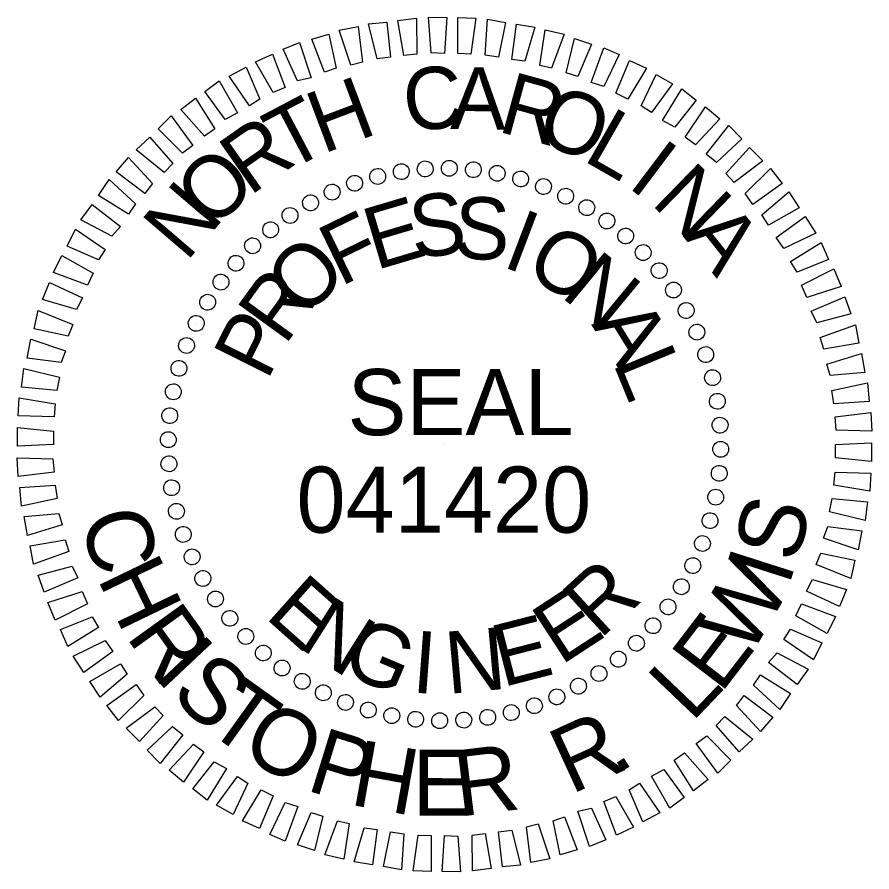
# Model space of a CAD drawing. Extents: x 573468 to 580768, y -57414 to -51768.
# Drawn here: x 580690.5 to 580768.1, y -52057.1 to -51979.5 of the extents above; entities that cross this region are included whole.
import ezdxf

# ---------------------------------------------------------------- set-up
doc = ezdxf.new("R2010")
doc.units = 0
doc.layers.add('Sheet PE Seal Cell', color=7, linetype='Continuous')

msp = doc.modelspace()

# ---------------------------------------------------------------- linework, layer by layer
at = {"layer": 'Sheet PE Seal Cell'}
for p, q in [((580725.379, -51993.539), (580725.379, -51993.539)), ((580727.529, -51993.239), (580727.529, -51993.239)), ((580729.729, -51993.189), (580729.729, -51993.189)), ((580731.929, -51993.339), (580731.929, -51993.339)), ((580723.179, -51993.939), (580723.179, -51993.939)), ((580734.079, -51993.689), (580734.079, -51993.689)), ((580736.179, -51994.139), (580736.179, -51994.139)), ((580721.079, -51994.539), (580721.079, -51994.539)), ((580738.279, -51994.839), (580738.279, -51994.839)), ((580719.079, -51995.339), (580719.079, -51995.339)), ((580740.279, -51995.739), (580740.279, -51995.739)), ((580717.129, -51996.339), (580717.129, -51996.339)), ((580742.229, -51996.739), (580742.229, -51996.739)), ((580715.229, -51997.489), (580715.229, -51997.489)), ((580744.029, -51997.989), (580744.029, -51997.989)), ((580713.479, -51998.739), (580713.479, -51998.739)), ((580745.779, -51999.339), (580745.779, -51999.339)), ((580711.829, -52000.239), (580711.829, -52000.239)), ((580747.329, -52000.839), (580747.329, -52000.839)), ((580710.329, -52001.789), (580710.329, -52001.789)), ((580748.829, -52002.489), (580748.829, -52002.489)), ((580708.979, -52003.539), (580708.979, -52003.539)), ((580750.079, -52004.239), (580750.079, -52004.239)), ((580707.729, -52005.339), (580707.729, -52005.339)), ((580751.229, -52006.139), (580751.229, -52006.139)), ((580706.729, -52007.289), (580706.729, -52007.289)), ((580752.229, -52008.089), (580752.229, -52008.089)), ((580705.829, -52009.289), (580705.829, -52009.289)), ((580753.029, -52010.089), (580753.029, -52010.089)), ((580705.129, -52011.389), (580705.129, -52011.389)), ((580753.629, -52012.189), (580753.629, -52012.189)), ((580704.679, -52013.489), (580704.679, -52013.489)), ((580754.029, -52014.389), (580754.029, -52014.389)), ((580704.329, -52015.639), (580704.329, -52015.639)), ((580754.329, -52016.539), (580754.329, -52016.539)), ((580704.179, -52017.839), (580704.179, -52017.839)), ((580729.279, -52018.289), (580729.279, -52018.289)), ((580754.379, -52018.739), (580754.379, -52018.739)), ((580704.229, -52020.039), (580704.229, -52020.039)), ((580754.229, -52020.939), (580754.229, -52020.939)), ((580704.529, -52022.189), (580704.529, -52022.189)), ((580753.879, -52023.089), (580753.879, -52023.089)), ((580704.929, -52024.389), (580704.929, -52024.389)), ((580753.429, -52025.189), (580753.429, -52025.189)), ((580705.529, -52026.489), (580705.529, -52026.489)), ((580752.729, -52027.289), (580752.729, -52027.289)), ((580706.329, -52028.489), (580706.329, -52028.489)), ((580751.829, -52029.289), (580751.829, -52029.289)), ((580707.329, -52030.439), (580707.329, -52030.439)), ((580750.829, -52031.239), (580750.829, -52031.239)), ((580708.479, -52032.339), (580708.479, -52032.339)), ((580749.579, -52033.039), (580749.579, -52033.039)), ((580709.729, -52034.089), (580709.729, -52034.089)), ((580748.229, -52034.789), (580748.229, -52034.789)), ((580711.229, -52035.739), (580711.229, -52035.739)), ((580746.729, -52036.339), (580746.729, -52036.339)), ((580712.779, -52037.239), (580712.779, -52037.239)), ((580745.079, -52037.839), (580745.079, -52037.839)), ((580714.529, -52038.589), (580714.529, -52038.589)), ((580743.329, -52039.089), (580743.329, -52039.089)), ((580716.329, -52039.839), (580716.329, -52039.839)), ((580718.279, -52040.839), (580718.279, -52040.839)), ((580741.429, -52040.239), (580741.429, -52040.239)), ((580739.479, -52041.239), (580739.479, -52041.239)), ((580720.279, -52041.739), (580720.279, -52041.739)), ((580722.379, -52042.439), (580722.379, -52042.439)), ((580737.479, -52042.039), (580737.479, -52042.039)), ((580724.479, -52042.889), (580724.479, -52042.889)), ((580733.179, -52043.039), (580733.179, -52043.039)), ((580735.379, -52042.639), (580735.379, -52042.639)), ((580726.629, -52043.239), (580726.629, -52043.239)), ((580728.829, -52043.389), (580728.829, -52043.389)), ((580731.029, -52043.339), (580731.029, -52043.339))]:
    msp.add_line(p, q, dxfattribs=at)
for points in [[(580728.079, -51982.739), (580727.829, -51979.489), (580729.479, -51979.539), (580729.279, -51982.789)], [(580730.479, -51982.789), (580730.479, -51979.539), (580732.129, -51979.589), (580731.679, -51982.839)], [(580720.779, -51983.839), (580719.729, -51980.689), (580721.429, -51980.339), (580721.829, -51983.589)], [(580723.179, -51983.289), (580722.379, -51980.089), (580724.029, -51979.939), (580724.379, -51983.139)], [(580725.579, -51982.989), (580725.029, -51979.789), (580726.729, -51979.589), (580726.779, -51982.839)], [(580732.979, -51982.939), (580733.179, -51979.689), (580734.829, -51979.989), (580734.179, -51983.139)], [(580735.379, -51983.339), (580735.829, -51980.139), (580737.479, -51980.389), (580736.579, -51983.489)], [(580718.379, -51984.489), (580717.229, -51981.489), (580718.779, -51981.039), (580719.429, -51984.139)], [(580737.929, -51983.889), (580738.429, -51980.639), (580740.129, -51981.039), (580738.979, -51984.139)], [(580715.929, -51985.289), (580714.629, -51982.389), (580716.129, -51981.789), (580717.179, -51984.989)], [(580740.329, -51984.539), (580741.079, -51981.439), (580742.629, -51981.939), (580741.379, -51984.889)], [(580742.579, -51985.439), (580743.729, -51982.289), (580745.129, -51982.889), (580743.729, -51985.789)], [(580713.729, -51986.339), (580712.129, -51983.539), (580713.679, -51982.839), (580714.829, -51985.889)], [(580744.829, -51986.389), (580746.079, -51983.439), (580747.629, -51984.139), (580745.929, -51986.939)], [(580711.579, -51987.539), (580709.729, -51984.839), (580711.279, -51984.039), (580712.529, -51986.939)], [(580747.129, -51987.539), (580748.479, -51984.689), (580749.979, -51985.539), (580748.079, -51988.139)], [(580709.379, -51988.789), (580707.529, -51986.239), (580708.829, -51985.289), (580710.479, -51988.189)], [(580749.079, -51988.889), (580750.829, -51985.989), (580752.129, -51987.039), (580750.179, -51989.489)], [(580707.479, -51990.289), (580705.329, -51987.889), (580706.679, -51986.839), (580708.429, -51989.639)], [(580751.129, -51990.389), (580752.979, -51987.639), (580754.279, -51988.739), (580752.079, -51991.089)], [(580705.479, -51991.839), (580703.279, -51989.639), (580704.479, -51988.439), (580706.429, -51991.139)], [(580753.029, -51991.939), (580755.079, -51989.339), (580756.279, -51990.539), (580753.979, -51992.689)], [(580703.829, -51993.589), (580701.279, -51991.539), (580702.529, -51990.389), (580704.629, -51992.789)], [(580754.829, -51993.689), (580756.979, -51991.339), (580758.179, -51992.539), (580755.579, -51994.489)], [(580702.079, -51995.489), (580699.479, -51993.539), (580700.579, -51992.239), (580702.779, -51994.589)], [(580756.579, -51995.489), (580758.879, -51993.239), (580759.929, -51994.589), (580757.279, -51996.489)], [(580700.579, -51997.389), (580697.879, -51995.689), (580698.829, -51994.239), (580701.229, -51996.439)], [(580758.079, -51997.439), (580760.529, -51995.339), (580761.479, -51996.789), (580758.679, -51998.389)], [(580699.079, -51999.389), (580696.279, -51997.889), (580697.279, -51996.489), (580699.879, -51998.489)], [(580759.379, -51999.489), (580762.029, -51997.589), (580762.979, -51999.089), (580760.079, -52000.489)], [(580697.879, -52001.539), (580695.029, -52000.289), (580695.779, -51998.739), (580698.479, -52000.589)], [(580760.679, -52001.689), (580763.479, -51999.939), (580764.129, -52001.489), (580761.279, -52002.639)], [(580696.879, -52003.839), (580693.779, -52002.689), (580694.529, -52001.139), (580697.379, -52002.739)], [(580761.679, -52003.839), (580764.629, -52002.339), (580765.279, -52003.939), (580762.179, -52004.939)], [(580695.879, -52006.039), (580692.779, -52005.139), (580693.429, -52003.589), (580696.429, -52004.989)], [(580762.579, -52006.189), (580765.629, -52004.889), (580766.179, -52006.439), (580763.079, -52007.239)], [(580695.129, -52008.439), (580692.029, -52007.789), (580692.379, -52006.139), (580695.529, -52007.389)], [(580763.379, -52008.589), (580766.579, -52007.439), (580766.879, -52009.089), (580763.729, -52009.639)], [(580694.479, -52010.839), (580691.379, -52010.439), (580691.729, -52008.739), (580694.879, -52009.789)], [(580763.979, -52010.989), (580767.129, -52010.039), (580767.429, -52011.739), (580764.279, -52012.039)], [(580694.079, -52013.389), (580690.879, -52013.089), (580691.079, -52011.389), (580694.329, -52012.189)], [(580764.429, -52013.389), (580767.679, -52012.689), (580767.829, -52014.389), (580764.629, -52014.589)], [(580693.829, -52015.789), (580690.579, -52015.689), (580690.679, -52014.039), (580693.929, -52014.589)], [(580764.729, -52015.789), (580767.979, -52015.389), (580768.079, -52017.089), (580764.829, -52016.989)], [(580693.779, -52018.289), (580690.529, -52018.439), (580690.529, -52016.739), (580693.779, -52017.089)], [(580764.779, -52018.289), (580768.029, -52018.139), (580768.029, -52019.839), (580764.779, -52019.489)], [(580693.829, -52020.789), (580690.579, -52021.189), (580690.479, -52019.489), (580693.729, -52019.589)], [(580764.729, -52020.789), (580767.979, -52020.889), (580767.879, -52022.539), (580764.629, -52021.989)], [(580694.129, -52023.189), (580690.879, -52023.889), (580690.729, -52022.189), (580693.929, -52021.989)], [(580764.479, -52023.189), (580767.679, -52023.489), (580767.479, -52025.189), (580764.229, -52024.389)], [(580694.579, -52025.589), (580691.429, -52026.539), (580691.129, -52024.839), (580694.279, -52024.539)], [(580764.079, -52025.739), (580767.179, -52026.139), (580766.829, -52027.839), (580763.679, -52026.789)], [(580695.179, -52027.989), (580691.979, -52029.139), (580691.679, -52027.489), (580694.829, -52026.939)], [(580763.429, -52028.139), (580766.529, -52028.789), (580766.179, -52030.439), (580763.029, -52029.189)], [(580695.979, -52030.389), (580692.929, -52031.689), (580692.379, -52030.139), (580695.479, -52029.339)], [(580762.679, -52030.539), (580765.779, -52031.439), (580765.129, -52032.989), (580762.129, -52031.589)], [(580696.879, -52032.739), (580693.929, -52034.239), (580693.279, -52032.639), (580696.379, -52031.639)], [(580761.679, -52032.739), (580764.779, -52033.889), (580764.029, -52035.439), (580761.179, -52033.839)], [(580697.879, -52034.889), (580695.079, -52036.639), (580694.429, -52035.089), (580697.279, -52033.939)], [(580760.679, -52035.039), (580763.529, -52036.289), (580762.779, -52037.839), (580760.079, -52035.989)], [(580699.179, -52037.089), (580696.529, -52038.989), (580695.579, -52037.489), (580698.479, -52036.089)], [(580759.479, -52037.189), (580762.279, -52038.689), (580761.279, -52040.089), (580758.679, -52038.089)], [(580700.479, -52039.139), (580698.029, -52041.239), (580697.079, -52039.789), (580699.879, -52038.189)], [(580757.979, -52039.189), (580760.679, -52040.889), (580759.729, -52042.339), (580757.329, -52040.139)], [(580701.979, -52041.089), (580699.679, -52043.339), (580698.629, -52041.989), (580701.279, -52040.089)], [(580756.479, -52041.089), (580759.079, -52043.039), (580757.979, -52044.339), (580755.779, -52041.989)], [(580703.729, -52042.889), (580701.579, -52045.239), (580700.379, -52044.039), (580702.979, -52042.089)], [(580754.729, -52042.989), (580757.279, -52045.039), (580756.029, -52046.189), (580753.929, -52043.789)], [(580705.529, -52044.639), (580703.479, -52047.239), (580702.279, -52046.039), (580704.579, -52043.889)], [(580753.079, -52044.739), (580755.279, -52046.939), (580754.079, -52048.139), (580752.129, -52045.439)], [(580707.429, -52046.189), (580705.579, -52048.939), (580704.279, -52047.839), (580706.479, -52045.489)], [(580751.079, -52046.289), (580753.229, -52048.689), (580751.879, -52049.739), (580750.129, -52046.939)], [(580709.479, -52047.689), (580707.729, -52050.589), (580706.429, -52049.539), (580708.379, -52047.089)], [(580749.179, -52047.789), (580751.029, -52050.339), (580749.729, -52051.289), (580748.079, -52048.389)], [(580711.429, -52049.039), (580710.079, -52051.889), (580708.579, -52051.039), (580710.479, -52048.439)], [(580746.979, -52049.039), (580748.829, -52051.739), (580747.279, -52052.539), (580746.029, -52049.639)], [(580713.729, -52050.189), (580712.479, -52053.139), (580710.929, -52052.439), (580712.629, -52049.639)], [(580715.979, -52051.139), (580714.829, -52054.289), (580713.429, -52053.689), (580714.829, -52050.789)], [(580744.829, -52050.239), (580746.429, -52053.039), (580744.879, -52053.739), (580743.729, -52050.689)], [(580718.229, -52052.039), (580717.479, -52055.139), (580715.929, -52054.639), (580717.179, -52051.689)], [(580742.629, -52051.289), (580743.929, -52054.189), (580742.429, -52054.789), (580741.379, -52051.589)], [(580720.629, -52052.689), (580720.129, -52055.939), (580718.429, -52055.539), (580719.579, -52052.439)], [(580740.179, -52052.089), (580741.329, -52055.089), (580739.779, -52055.539), (580739.129, -52052.439)], [(580723.179, -52053.239), (580722.729, -52056.439), (580721.079, -52056.189), (580721.979, -52053.089)], [(580735.379, -52053.289), (580736.179, -52056.489), (580734.529, -52056.639), (580734.179, -52053.439)], [(580737.779, -52052.739), (580738.829, -52055.889), (580737.129, -52056.239), (580736.729, -52052.989)], [(580725.579, -52053.639), (580725.379, -52056.889), (580723.729, -52056.589), (580724.379, -52053.439)], [(580728.079, -52053.789), (580728.079, -52057.039), (580726.429, -52056.989), (580726.879, -52053.739)], [(580730.479, -52053.839), (580730.729, -52057.089), (580729.079, -52057.039), (580729.279, -52053.789)], [(580732.979, -52053.589), (580733.529, -52056.789), (580731.829, -52056.989), (580731.779, -52053.739)]]:
    msp.add_lwpolyline(points, close=True, dxfattribs=at)
for centre, major_axis in [((580725.355, -51993.517), (-0.113, 0.711)), ((580727.529, -51993.27), (-0.05, 0.718)), ((580729.716, -51993.212), (0.013, 0.72)), ((580731.9, -51993.346), (0.075, 0.716)), ((580723.211, -51993.954), (-0.174, 0.699)), ((580734.064, -51993.669), (0.137, 0.707)), ((580736.192, -51994.18), (0.198, 0.692)), ((580721.113, -51994.575), (-0.234, 0.681)), ((580738.266, -51994.874), (0.258, 0.672)), ((580719.078, -51995.377), (-0.293, 0.658)), ((580740.273, -51995.747), (0.316, 0.647)), ((580717.12, -51996.353), (-0.349, 0.63)), ((580742.196, -51996.791), (0.371, 0.617)), ((580715.254, -51997.496), (-0.403, 0.597)), ((580744.02, -51997.998), (0.423, 0.582)), ((580713.495, -51998.798), (-0.453, 0.56)), ((580745.733, -51999.36), (0.472, 0.543)), ((580711.857, -52000.248), (-0.5, 0.518)), ((580747.32, -52000.867), (0.518, 0.5)), ((580710.35, -52001.835), (-0.543, 0.472)), ((580748.769, -52002.505), (0.56, 0.453)), ((580708.988, -52003.547), (-0.582, 0.423)), ((580750.071, -52004.264), (0.597, 0.403)), ((580707.781, -52005.371), (-0.617, 0.371)), ((580751.214, -52006.13), (0.63, 0.349)), ((580706.737, -52007.294), (-0.647, 0.316)), ((580752.19, -52008.088), (0.658, 0.293)), ((580705.864, -52009.301), (-0.672, 0.258)), ((580752.992, -52010.123), (0.681, 0.234)), ((580705.17, -52011.376), (-0.692, 0.198)), ((580753.614, -52012.221), (0.699, 0.174)), ((580704.659, -52013.503), (-0.707, 0.137)), ((580754.05, -52014.365), (0.711, 0.113)), ((580704.336, -52015.667), (-0.716, 0.075)), ((580754.297, -52016.539), (0.718, 0.05)), ((580704.202, -52017.851), (-0.72, 0.013)), ((580754.355, -52018.726), (0.72, -0.013)), ((580704.26, -52020.038), (-0.718, -0.05)), ((580754.221, -52020.91), (0.716, -0.075)), ((580704.507, -52022.212), (-0.711, -0.113)), ((580753.898, -52023.074), (0.707, -0.137)), ((580704.944, -52024.356), (-0.699, -0.174)), ((580753.387, -52025.202), (0.692, -0.198)), ((580705.565, -52026.454), (-0.681, -0.234)), ((580752.693, -52027.276), (0.672, -0.258)), ((580706.367, -52028.49), (-0.658, -0.293)), ((580751.82, -52029.283), (0.647, -0.316)), ((580707.343, -52030.448), (-0.63, -0.349)), ((580750.776, -52031.206), (0.617, -0.371)), ((580708.486, -52032.313), (-0.597, -0.403)), ((580749.569, -52033.03), (0.582, -0.423)), ((580709.788, -52034.072), (-0.56, -0.453)), ((580748.207, -52034.743), (0.543, -0.472)), ((580711.238, -52035.711), (-0.518, -0.5)), ((580746.701, -52036.33), (0.5, -0.518)), ((580712.825, -52037.217), (-0.472, -0.543)), ((580745.062, -52037.779), (0.453, -0.56)), ((580714.537, -52038.579), (-0.423, -0.582)), ((580743.303, -52039.081), (0.403, -0.597)), ((580716.361, -52039.786), (-0.371, -0.617)), ((580718.284, -52040.83), (-0.316, -0.647)), ((580741.438, -52040.224), (0.349, -0.63)), ((580739.48, -52041.2), (0.293, -0.658)), ((580720.291, -52041.703), (-0.258, -0.672)), ((580722.366, -52042.397), (-0.198, -0.692)), ((580737.444, -52042.002), (0.234, -0.681)), ((580724.493, -52042.908), (-0.137, -0.707)), ((580733.202, -52043.06), (0.113, -0.711)), ((580735.346, -52042.624), (0.174, -0.699)), ((580726.657, -52043.231), (-0.075, -0.716)), ((580728.841, -52043.365), (-0.013, -0.72)), ((580731.028, -52043.307), (0.05, -0.718))]:
    msp.add_ellipse(centre, major_axis=major_axis, ratio=0.999708, dxfattribs=at)

# ---------------------------------------------------------------- texts
for s, height, rotation, p in [('C', 5.638, 6.21987, (580725.829, -51989.939)), ('A', 5.638, 359.02032, (580729.779, -51989.639)), ('H', 5.638, 20.61948, (580718.229, -51991.939)), ('R', 5.638, 344.6211, (580733.979, -51989.839)), ('T', 5.638, 27.81977, (580714.979, -51993.589)), ('O', 5.638, 337.42116, (580737.329, -51990.589)), ('L', 5.638, 330.22088, (580741.729, -51992.439)), ('R', 5.639, 35.02051, (580711.579, -51995.789)), ('I', 5.638, 323.02014, (580745.779, -51994.839)), ('O', 5.639, 42.22174, (580708.129, -51998.889)), ('N', 5.639, 315.81891, (580747.929, -51996.389)), ('N', 5.639, 49.4235, (580705.829, -52001.789)), ('E', 5.638, 16.61107, (580723.029, -52002.489)), ('S', 5.638, 7.25561, (580726.479, -52001.439)), ('S', 5.638, 357.9004, (580730.079, -52001.389)), ('F', 5.638, 25.96703, (580719.829, -52003.989)), ('I', 5.638, 339.1896, (580734.379, -52002.089)), ('A', 5.639, 308.61715, (580750.879, -51999.339)), ('O', 5.638, 329.83348, (580736.379, -52002.789)), ('O', 5.639, 44.68124, (580716.529, -52006.939)), ('N', 5.639, 320.47661, (580739.729, -52004.789)), ('R', 5.639, 54.03965, (580714.779, -52009.389)), ('P', 5.639, 63.39889, (580713.179, -52012.589)), ('A', 5.639, 301.76027, (580742.579, -52007.389)), ('L', 5.639, 292.40085, (580744.529, -52010.839)), ('SEAL', 5.9982, 360, (580720.48, -52017.44)), ('S', 5.998, 76.05447, (580761.307, -52029.145)), ('C', 5.998, 286.20197, (580696.13, -52024.986)), ('H', 5.998, 295.78413, (580697.707, -52030.41)), ('W', 5.998, 59.71844, (580756.96, -52037.716)), ('I', 5.998, 72.25252, (580760.516, -52031.245)), ('R', 5.639, 42.48141, (580743.379, -52036.039)), ('E', 5.638, 318.27689, (580712.879, -52033.939)), ('E', 5.638, 33.12409, (580739.829, -52038.389)), ('N', 5.639, 327.63396, (580715.879, -52036.639)), ('R', 5.998, 305.76811, (580700.287, -52035.7)), ('E', 5.638, 14.41176, (580734.529, -52040.339)), ('E', 5.998, 52.60911, (580754.343, -52040.992)), ('G', 5.638, 336.99024, (580719.679, -52038.889)), ('I', 5.638, 355.7012, (580726.229, -52040.789)), ('N', 5.638, 5.05639, (580729.579, -52040.939)), ('I', 5.998, 313.24837, (580702.801, -52039.326)), ('S', 5.998, 317.05032, (580704.254, -52041.036)), ('L', 5.998, 46.33434, (580751.711, -52043.596)), ('T', 5.998, 324.37603, (580707.359, -52044.041)), ('O', 5.998, 331.17627, (580710.562, -52046.455)), ('R', 5.998, 24.61995, (580740.756, -52050.099)), ('P', 5.998, 342.73667, (580716.586, -52049.635)), ('H', 5.998, 349.84601, (580720.563, -52050.964)), ('E', 5.998, 359.82999, (580726.361, -52051.981)), ('R', 5.998, 6.93933, (580730.553, -52052.083)), ('.', 5.998, 32.10021, (580744.8, -52048.335))]:
    msp.add_text(s, height=height, rotation=rotation, dxfattribs=at).set_placement(p)
msp.add_text('041420', height=5.9982, dxfattribs=at).set_placement((580715.839, -52026.297))

doc.saveas('drawing.dxf')
